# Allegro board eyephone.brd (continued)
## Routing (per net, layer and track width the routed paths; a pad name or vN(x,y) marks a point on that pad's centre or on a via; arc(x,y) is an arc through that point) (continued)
NET16: length 39.3
  TOP w0.15: U2.6 v1(22.68,74.27)
  GND w0.15: v1(36.51,50.51) v2(36.51,52.5)
  VCC w0.15: v3(37.21,61.09) 30.72,67.57 v3(25.43,67.57)
  BOTTOM w0.15: v3(25.43,67.57) 25.43,68.77 25,69.2 U4.5 23.73,69.2 22.68,70.24 v1(22.68,74.27) ; v1(36.51,50.51) 37.21,51.21 U19.10 v3(37.21,61.09)
NET17: length 45.6
  TOP w0.15: v2(16.28,57.44) 16.28,52.8 16.16,52.67 7.03,52.67 6.57,52.22 v2(6.57,51.64)
  GND w0.15: v1(4.52,28.56) 4.52,44.32 6.23,46.04 6.38,46.04 6.57,46.23 v2(6.57,51.64) ; v2(16.28,57.44) 16.28,62.77 v2(16.59,63.08)
  BOTTOM w0.15: U6.V21 v1(4.52,28.56)
NET20: length 51.7
  TOP w0.15: U17.32 v1(4.97,61.3) ; U13.10 v1(17.24,61.3)
  VCC w0.15: v1(17.24,61.3) v1(4.97,61.3)
  BOTTOM w0.15: U6.W19 6.62,28.08 6.62,37.73 6.22,38.13 4.22,38.13 4.22,60.55 v1(4.97,61.3)
NET21: length 28.1
  TOP w0.15: U17.16 10.57,51.05 11.45,50.18 v1(13.65,50.18)
  BOTTOM w0.15: v1(13.65,50.18) 14.71,49.12 14.71,28.33 15.03,28.02 15.68,28.02 U6.W10
NET24: length 100.2
  TOP w0.15: U16.14 v2(32.21,76.54) ; U17.18 v1(14.05,53.88)
  GND w0.15: v1(33.1,21.93) 33.1,15.01 v2(33.17,14.94) v2(34.44,14.94) ; v1(32.21,69.59) v2(32.21,76.54)
  VCC w0.15: v3(15.72,67.9) 25.46,67.9 v3(27.15,69.59) v1(32.21,69.59)
  BOTTOM w0.15: U6.AA4 22.6,25.56 ; 22.6,25.56 22.6,24.89 24.01,24.89 26.97,21.93 v1(33.1,21.93) ; 22.6,25.56 22.6,31.77 22.28,32.09 20.97,32.09 18.62,34.44 18.62,45.72 18.3,46.04 15.28,46.04 15.15,46.17 15.15,53.6 14.87,53.88 ; 14.87,53.88 v1(14.05,53.88) ; 14.87,53.88 14.87,63.3 15.72,64.15 v3(15.72,67.9)
NET25: length 81.8
  TOP w0.15: U11.11 34.44,23.04 33.17,24.31 v1(15.62,24.31) ; v1(12.28,64.29) 9.98,64.29 7.37,61.68 U17.29
  BOTTOM w0.15: U3.2 15.09,71.15 12.28,68.34 v1(12.28,64.29) 12.28,46.19 12.47,45.99 13.37,45.99 13.62,45.74 13.62,26.45 13.94,26.13 15.62,26.13 ; U6.Y10 15.62,26.56 15.62,26.13 ; 15.62,26.13 v1(15.62,24.31)
NET28: length 78.1
  TOP w0.15: v1(8.56,30.07) v2(17.46,30.07) ; v2(19.72,15.6) 20.93,15.6 21.16,15.37 U14.5 22.38,15.37 23.95,16.94 v2(36.98,16.94)
  GND w0.15: v2(36.98,16.94) v2(36.98,14.94) ; v1(17.46,49.77) v2(17.46,30.07) 17.46,17.86 v2(19.72,15.6) ; v2(17.46,60.12) 18.33,59.25 v1(18.33,56.02)
  VCC w0.15: v1(8.56,30.07) 7.05,28.56 v3(6.14,28.56)
  BOTTOM w0.15: v1(17.46,49.77) 18.33,50.64 v1(18.33,56.02)
NET30: length 38.2
  TOP w0.15: U16.2 30.67,77.19 32.67,75.19 v1(34.46,75.19) 34.46,74.72 34.58,74.59 U16.11 ; U1.2 v1(11.52,76.86) ; U2.2 v1(20.91,76.86)
  VCC w0.15: v3(11.52,76.2) v1(11.52,76.86) v1(20.91,76.86) 29.47,76.86 v3(31.15,75.19) v1(34.46,75.19)
  BOTTOM w0.15: U20.28 31,76.05 31.15,75.89 v3(31.15,75.19) ; U20.1 v1(34.46,75.19)
NET31: length 14.3
  TOP w0.15: U1.3 11.54,76.22 12.84,77.52 U1.14 17.41,77.52 18.11,76.82 18.11,76.73 18.62,76.22 U2.3 21.45,76.22 v1(21.46,76.2)
  BOTTOM w0.15: R13.1 v1(21.46,76.2)
NET32: length 15.9
  TOP w0.15: U1.4 v1(11.4,75.56) ; v1(21.47,74.93) 20.84,75.56 U2.4
  VCC w0.15: v1(21.47,74.93) 20.84,75.56 v1(11.4,75.56)
  BOTTOM w0.15: R17.1 v1(21.47,74.93)
NET33: length 56.6
  TOP w0.15: v2(17.06,38.56) v1(20.29,38.56) ; v1(26.8,38.56) 26.8,45.26 29.6,48.05 34.67,48.05 35.94,49.32 35.94,49.38 36.41,49.85 R11.2 v1(36.97,49.91)
  GND w0.15: v2(16.64,15.37) 17.06,15.79 v2(17.06,38.56)
  VCC w0.15: v1(26.8,38.56) v3(24.14,38.56) v1(20.29,38.56)
  BOTTOM w0.15: U19.12 35.61,50.8 36.49,49.91 v1(36.97,49.91)
NET34: length 9.2
  TOP w0.15: U16.10 v1(31.21,73.94)
  BOTTOM w0.15: v1(31.21,73.94) 30.13,73.94 28.88,75.19 U20.24
PECL1_N: length 88.3
  TOP w0.15: v1(13.05,24.96) 13.11,25.02 34.91,25.02 v2(34.97,25.09) ; v2(11.72,61.53) 11.66,61.6 10.48,61.6 10.05,62.03 8.7,62.03 8.67,62 8.21,62 v2(8.02,61.81)
  GND w0.15: v2(35.71,20.62) 35.71,20.98 35.91,21.17 35.91,22.29 35.04,23.16 35.04,25.02 v2(34.97,25.09) ; v2(3.53,57.08) 4.91,58.46 5.63,58.46 8.24,61.06 8.24,61.6 v2(8.02,61.81) 8.21,62 8.21,62.47 8.24,62.5 8.24,68.98 8.14,69.09 v1(8.14,69.68) ; v1(13.05,24.96) 13.05,25.41 13.15,25.51 13.15,46.26 11.14,48.28 11.14,58.62 11.79,59.28 11.79,61.47 v2(11.72,61.53)
  VCC w0.15: v1(13.05,24.96) 12.54,24.96 12.29,25.22 12.29,25.71 v3(13.14,26.56)
  BOTTOM w0.15: U3.11 8.97,69.85 8.8,69.68 v1(8.14,69.68)
PECL1_P: length 97.5
  TOP w0.15: v1(12.94,75.15) 12.94,75.64 13.51,76.22 U1.12 ; v1(13.55,24.46) 13.82,24.72 35.34,24.72 v2(35.4,24.66) ; v2(12.15,61.96) 12.09,61.9 10.61,61.9 10.18,62.33 v2(8.54,62.33) ; U11.9 v2(36.4,20.62)
  GND w0.15: v1(13.55,24.46) 13.55,25.05 13.45,25.15 13.45,46.38 11.44,48.4 11.44,58.5 12.09,59.15 12.09,61.9 v2(12.15,61.96) ; v2(9.77,60.12) 8.54,61.36 v2(8.54,62.33) 8.54,68.63 8.64,68.73 v1(8.64,69.17) ; v2(35.4,24.66) 35.34,24.59 35.34,23.28 36.21,22.41 36.21,21.17 36.4,20.98 v2(36.4,20.62)
  VCC w0.15: v1(13.55,24.46) 12.41,24.46 11.99,24.88 11.99,28.71 v3(11.14,29.56)
  BOTTOM w0.15: v1(8.64,69.17) 9.98,69.17 U3.10 10.62,69.2 12.94,71.52 v1(12.94,75.15)
PECL2_N: length 50.4
  TOP w0.15: v2(16.3,31.2) 16.37,31.27 18.57,31.27 18.67,31.17 v1(19.27,31.17)
  GND w0.15: v2(16.3,31.2) 16.37,31.27 16.37,49.9 13.19,53.08 v2(12.02,53.08) ; v2(31.9,20.62) 31.9,20.98 32.1,21.17 32.1,21.52 30.68,22.93 25.65,22.93 23.76,24.83 23.76,27.59 20.08,31.27 19.81,31.27 19.71,31.17 v1(19.27,31.17)
  VCC w0.15: v1(19.27,31.17) 18.99,30.89 18.99,30.41 v3(17.14,28.56)
PECL2_P: length 104.4
  TOP w0.15: v2(16.73,31.64) 16.8,31.57 18.22,31.57 18.32,31.67 v1(18.76,31.67) ; U11.12 v2(32.59,20.62)
  GND w0.15: v2(16.73,31.64) 16.67,31.7 16.67,50.05 17.93,51.31 20.79,51.31 21.12,51.64 v2(22.26,51.64) ; v1(18.76,31.67) 19.35,31.67 19.46,31.57 20.2,31.57 24.06,27.71 24.06,24.95 25.78,23.23 30.81,23.23 32.4,21.65 32.4,21.17 32.59,20.98 v2(32.59,20.62)
  VCC w0.15: v1(18.76,31.67) 19.35,31.67 19.68,31.34 19.68,30.99 19.29,30.6 19.29,28.89 20.62,27.56 v3(21.14,27.56) 23.79,24.91 v3(24.74,24.91)
  BOTTOM w0.15: v3(24.74,24.91) 25.81,24.91 25.88,24.98 25.88,55.03 29.4,58.54 U20.15
PHASE_N: length 28
  TOP w0.15: U12.3 v1(22.91,60.77)
  BOTTOM w0.15: v1(22.91,60.77) 21.93,60.77 19.71,58.54 19.71,42.13 U6.E7
PHASE_P: length 27.4
  TOP w0.15: U12.2 v2(27.6,61.42)
  GND w0.15: v1(18.14,40.94) 18.95,40.94 24.24,46.23 24.24,58.06 v2(27.6,61.42)
  BOTTOM w0.15: U6.E8 v1(18.14,40.94)

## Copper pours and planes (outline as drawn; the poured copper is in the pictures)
Net_257 on TOP (solid shape): 38.71,54.66 31.7,54.66 31.7,61.67 38.71,61.67
